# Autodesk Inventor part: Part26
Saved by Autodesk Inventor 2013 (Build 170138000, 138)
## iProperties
Created: 2012-07
Part Number: Part26
Material: Generic
Document SubType Name: Modeling
Designer: Paul
Density: 1 g/cm^3
Author: Paul
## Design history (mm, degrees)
node "User Library-Arduino Mega.SAT1"
body "Solid1"
node "Base1"
